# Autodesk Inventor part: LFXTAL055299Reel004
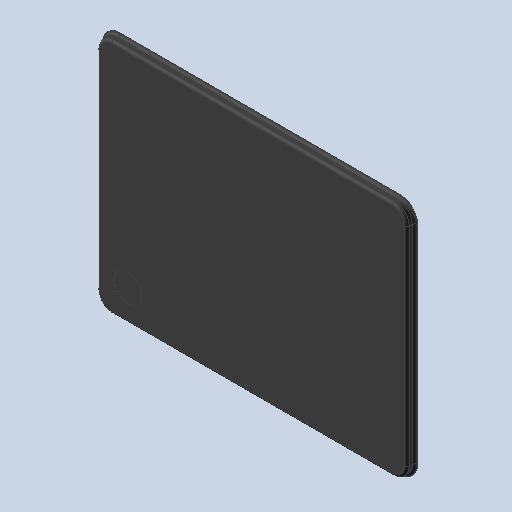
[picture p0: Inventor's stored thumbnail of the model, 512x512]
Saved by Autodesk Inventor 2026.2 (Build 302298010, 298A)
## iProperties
Created: 2026-10
Part Number: LFXTAL055299Reel004
Material: Générique
Document SubType Name: Modeling
Designer: mel
Density: 1 g/cm^3
Appearance: Par défaut
Author: mel
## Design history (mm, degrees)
feature "Base1"
node "Solide1"
